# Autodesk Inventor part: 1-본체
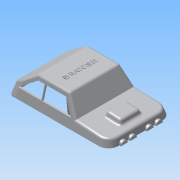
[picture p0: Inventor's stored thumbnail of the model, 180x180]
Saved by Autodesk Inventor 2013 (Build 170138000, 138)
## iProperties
Created: 2007-09
Part Number: 1-본체
Material: ABS 플라스틱
Document SubType Name: Modeling
Designer: Administrator
Density: 1 g/cm^3
Author: Administrator
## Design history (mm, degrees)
sketch "스케치1"
  geometry: L1 (-61, 38)-(61, 38); L2 (61, 38)-(61, -38); L3 (61, -38)-(-61, -38); L4 (-61, -38)-(-61, 38); 3 further points
  constraints: 8 end point, 2 midpoint, 2 parallel, 1 horizontal, 1 horizontal alignment, 1 perpendicular, 1 vertical alignment
  dimensions: "d0" = 122 distance of L2.end L3.end; "d2" = 76 distance of L1.end L2.end
extrude "돌출1" new body sketch "스케치1" distance "d3" = 30; taper "d4" = -15 deg
sketch "스케치2"
  geometry: L1 (61, 38)-(-61, 38) reference; L2 (-61, 38)-(-61, -38) reference; L3 (-61, -38)-(61, -38) reference; L4 (61, -38)-(61, 38) reference; L5 (-60, 37)-(60, 37); L6 (60, 37)-(60, -37); L7 (60, -37)-(-60, -37); L8 (-60, -37)-(-60, 37); 1 further point
  constraints: 8 end point, 3 other
  dimensions: "d5" = 1 distance between parallel lines of L1 L5
extrude "돌출2" join sketch "스케치2" distance "d6" = 1; taper "d7" = 0 deg
sketch "스케치3"
  geometry: L1 (-61, 0)-(-52.962, 30) reference; L2 (52.962, 30)-(-52.962, 30) reference; L3 (-58.856, 8)-(-19, 10.089); L4 (-19, 10.089)-(-6.558, 30); L5 (61, 0)-(52.962, 30) reference; L6 (31, 30)-(58.321, 10); L7 (60, -1)-(-60, -1) reference; L8 (61, 0)-(-61, 0) reference; L9 (-13.16, 10)-(-3.787, 25); L10 (-3.787, 25)-(20.84, 25); L11 (20.84, 25)-(20.84, 10); L12 (20.84, 10)-(-13.16, 10); L13 (21.856, 25)-(21.856, 10); L14 (21.856, 10)-(49.856, 10); L15 (49.856, 10)-(29.365, 25); L16 (29.365, 25)-(21.856, 25); 1 further point
  constraints: 22 end point, 4 horizontal, 4 point on line, 2 collinear, 2 parallel, 2 perpendicular
  dimensions: "d9" = 9 distance from line of L7 L3.start; "d11" = 125 deg angle of L4 L3; "d13" = 20 vertical distance of L6.start L6.end; "d14" = 3 deg angle of L8 L3; "d50" = 34 distance of L11.end L9.start; "d51" = 28 distance of L13.end L14.end; "d52" = 5 distance between parallel lines of L2 L10; "d53" = 5 distance between parallel lines of L6 L15; "d54" = 5 distance between parallel lines of L4 L9; "d55" = 15 distance of L10.end L11.end; "d56" = 42 horizontal distance of L3.end L1.start; "d57" = 30 horizontal distance of L5.start L6.start
extrude "돌출3" cut sketch "스케치3" stored distance "d15" = 1; taper "d16" = 0 deg
sketch "스케치4"
  geometry: L1 (0, 71.713)-(0, 0) reference; L2 (-28.441, 48.856)-(-8.441, 48.856); L3 (-8.441, 48.856)-(-8.441, 22.856); L4 (-8.441, 22.856)-(-28.441, 22.856); L5 (-28.441, 22.856)-(-28.441, 48.856); L6 (2.559, 73.856)-(2.559, -2.144) reference; 3 further points
  constraints: 8 end point, 2 midpoint, 2 parallel, 1 horizontal, 1 horizontal alignment, 1 perpendicular
  dimensions: "d17" = 26 distance of L2.end L3.end; "d19" = 20 distance of L3.end L4.end; "d20" = 11 distance between parallel lines of L6 L3
extrude "돌출4" join sketch "스케치4" distance "d21" = 5; taper "d22" = -20 deg
feature "쉘1" dims "d25" = 2
node "작업 평면3"
sketch "스케치7"
  geometry: L1 (-10, 0)-(10, 0); A1 r 4 centre (-21, 0) between (-17, 0) and (-25, 0); A2 r 4 centre (-10, 0) between (-6, 0) and (-14, 0); A3 r 4 centre (10, 0) between (14, 0) and (6, 0); A4 r 4 centre (21, 0) between (25, 0) and (17, 0); 5 further points
  constraints: 8 point on circle, 4 centre point, 3 equal radius, 2 end point, 2 point on line, 1 coincident, 1 horizontal, 1 midpoint, 12 other
  dimensions: "d33" = 4 radius of A1; "d35" = 11 distance of L1.start A1.centre; "d36" = 11 distance of A4.centre L1.end; "d37" = 20 distance of L1.end L1.start
extrude "돌출5" join sketch "스케치7" stored distance "d38" = 5; taper "d39" = 0 deg
extrude "돌출6" cut sketch "스케치3" stored distance "d58" = 5; taper "d59" = 0 deg
sketch "스케치10"
  geometry: L1 (-47.368, 9.78)-(-47.368, -9.78) reference; L2 (-47.368, -9.78)-(-33.828, -9.78) reference; L3 (-33.828, -9.78)-(-33.828, 9.78) reference; L4 (-33.828, 9.78)-(-47.368, 9.78) reference; L5 (-0.598, 22)-(-0.598, -22); C1 r 3 at (-40.598, 0); C2 r 3 at (39.402, 0); C3 r 3 at (-0.598, 22); C4 r 3 at (-0.598, -22); 4 further points
  constraints: 4 centre point, 3 equal radius, 3 horizontal alignment, 3 midpoint, 2 end point, 2 vertical alignment, 1 perpendicular
  dimensions: "d63" = 6 diameter of C1; "d65" = 40 horizontal distance of L5.end C1.centre; "d66" = 40 horizontal distance of C2.centre L5.end; "d67" = 44 distance of L5.start L5.end
extrude "돌출7" join sketch "스케치10" stored distance "d68" = 5; taper "d69" = 4 deg
fillet "모깎기1" dims "d74" = 3
fillet "모깎기2" dims "d75" = 3
fillet "모깎기4" dims "d77" = 3
fillet "모깎기5" dims "d78" = 3
fillet "모깎기6" dims "d79" = 3
fillet "모깎기7" dims "d80" = 12
fillet "모깎기8" dims "d81" = 12
fillet "모깎기9" dims "d82" = 12
fillet "모깎기10" dims "d83" = 12
sketch "스케치14"
  geometry: L1 (-61, -26.409)-(-61, 26.409) reference; 2 further points
  constraints: 1 horizontal alignment, 1 other
  dimensions: "d84" = 50 distance from line of L1 point (-11, 0)
feature "엠보싱1" sketch "스케치14" dims "d0" = 122, "d2" = 76, "d85" = 0.5, "d86" = 0
node "솔리드1"
node "투영된 루프2"
other parameters: "d32" = 63
